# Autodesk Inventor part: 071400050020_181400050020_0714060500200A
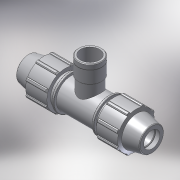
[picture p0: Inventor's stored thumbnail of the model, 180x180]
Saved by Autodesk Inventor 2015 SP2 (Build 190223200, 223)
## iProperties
Created: 2017-02
Part Number: 071400050020_181400050020_0714060500200A
Material: PVC-Piping
Description: PLASSON TEE WITH THREADED FEMALE OFFTAKE 50-2"-50
Document SubType Name: Modeling
Designer: KIM
Mass: 92.6774 g
Surface Area: 199.44 cm^2
Volume: 66.1981 cm^3
Density: 1.4 g/cm^3
Appearance: Smooth - White
Author: KIM
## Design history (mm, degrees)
derived "07140.ipt"
feature "Solid1::07140.ipt"
feature "Solid2::07140.ipt"
tag "TaggingFeature1"
body "Solid1"
other parameters: "d4" = 10.16667, "d5" = 29.28, "d7" = 96, "d11" = 4.06667, "d13" = 120 deg, "d15" = 12 deg, "d16" = 83.52, "d18" = 2.5, "d19" = 35 deg, "d20" = 17.5 deg, "d21" = 89.28, "d23" = 0, "d25" = 360 deg, "d27" = 1.92, "d33" = 1, "d42" = 43.92, "d43" = 2.88, "d46" = 1.5, "d68" = 7.32, "d76" = 56.656, "d80" = 1.69968, "d91" = 72, "d93" = 93, "d95" = 45, "d115" = 70.82, "d116" = 135 deg, "d117" = 65.1544, "d118" = 244, "d119" = 45, "d121" = 0, "d122" = 45, "d124" = 0, "d128" = 0, "d129" = 5, "d130" = 9, "d131" = 0.3, "d132" = 0.3, "d133" = 70.82, "E_" = 96, "l_" = 93, "Rp_" = 56.656, "H_" = 244
